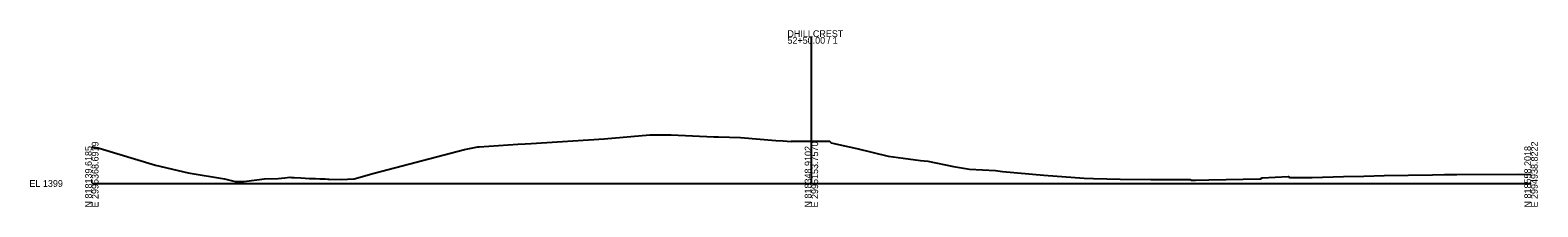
# Model space of a CAD drawing. Extents: x -26 to 603, y -10 to 2564.
# Drawn here: x -26 to 603, y 2490 to 2564 of the extents above; entities that cross this region are included whole.
import ezdxf

# ---------------------------------------------------------------- set-up
doc = ezdxf.new("R2010")
doc.units = 0
doc.layers.add('DESIGN - SHEET - Light Grid', color=7, linetype='Continuous')
doc.layers.add('SURVEY - GROUND - Top of Ground', color=7, linetype='Continuous')

msp = doc.modelspace()

# ---------------------------------------------------------------- linework, layer by layer
at = {"layer": 'DESIGN - SHEET - Light Grid'}
for p, q in [((300, 2500), (300, 2560.95)), ((0, 2500), (300, 2500)), ((300, 2500), (600, 2500))]:
    msp.add_line(p, q, dxfattribs=at)
at = {"layer": 'SURVEY - GROUND - Top of Ground'}
msp.add_lwpolyline([(0, 2515.29), (0.36, 2515.19), (3.02, 2514.66), (26.61, 2507.61), (40.15, 2504.47), (55.26, 2501.95), (59.77, 2500.79), (63.34, 2500.9), (68.75, 2501.46), (72.04, 2501.9), (77.68, 2502.11), (80.44, 2502.34), (82.55, 2502.59), (83.3, 2502.54), (84.36, 2502.48), (87.21, 2502.29), (90.8, 2502.14), (92.37, 2502.09), (93.23, 2502.07), (95.05, 2502), (96.67, 2501.92), (97.25, 2501.89), (98.46, 2501.83), (98.99, 2501.81), (104.3, 2501.61), (106.54, 2501.78), (109.35, 2501.99), (117.7, 2504.29), (155.36, 2514.09), (160.95, 2515.21), (161.54, 2515.29), (177.66, 2516.43), (180.62, 2516.46), (183.13, 2516.62), (213.65, 2518.57), (232.62, 2520.32), (240.35, 2520.19), (241.56, 2520.22), (259.27, 2519.45), (261.33, 2519.36), (270.41, 2519.15), (285.13, 2517.95), (288.2, 2517.75), (291.6, 2517.51), (291.69, 2517.66), (294.36, 2517.57), (299.66, 2517.63), (300, 2517.64), (302.49, 2517.65), (307.58, 2517.55), (308.19, 2516.93), (309.42, 2516.64), (311.28, 2516.2), (318.88, 2514.52), (331.98, 2511.36), (338.29, 2510.51), (345.53, 2509.54), (348.56, 2509.33), (359.27, 2507.11), (365.97, 2506.01), (376.74, 2505.36), (379.6, 2504.98), (396.96, 2503.53), (413.75, 2502.17), (417.66, 2502.11), (428.68, 2501.85), (441.51, 2501.61), (450.7, 2501.72), (457.85, 2501.69), (458.52, 2501.33), (460.15, 2501.33), (465.67, 2501.48), (487.16, 2501.91), (487.85, 2502.34), (498.78, 2502.85), (499.38, 2502.43), (508.74, 2502.55), (521.81, 2502.85), (530.23, 2503.06), (538.75, 2503.36), (558.99, 2503.59), (563.98, 2503.7), (565.57, 2503.75), (569.13, 2503.79), (594.58, 2503.9), (600, 2503.8)], dxfattribs=at)

# ---------------------------------------------------------------- texts
at = {"layer": 'DESIGN - SHEET - Light Grid'}
for s, p in [('52+50.00 / 1', (290, 2558.15)), ('DHILLCREST', (290, 2560.95)), ('EL 1399', (-26, 2498.6))]:
    msp.add_text(s, height=2.8, dxfattribs=at).set_placement(p)
for s, p in [('N 818139.6185', (0, 2490)), ('E 2995368.6919', (2.8, 2490)), ('N 818348.9102', (300, 2490)), ('E 2995153.7570', (302.8, 2490)), ('N 818558.2018', (600, 2490)), ('E 2994938.8222', (602.8, 2490))]:
    msp.add_text(s, height=2.8, rotation=90, dxfattribs=at).set_placement(p)

doc.saveas('drawing.dxf')
